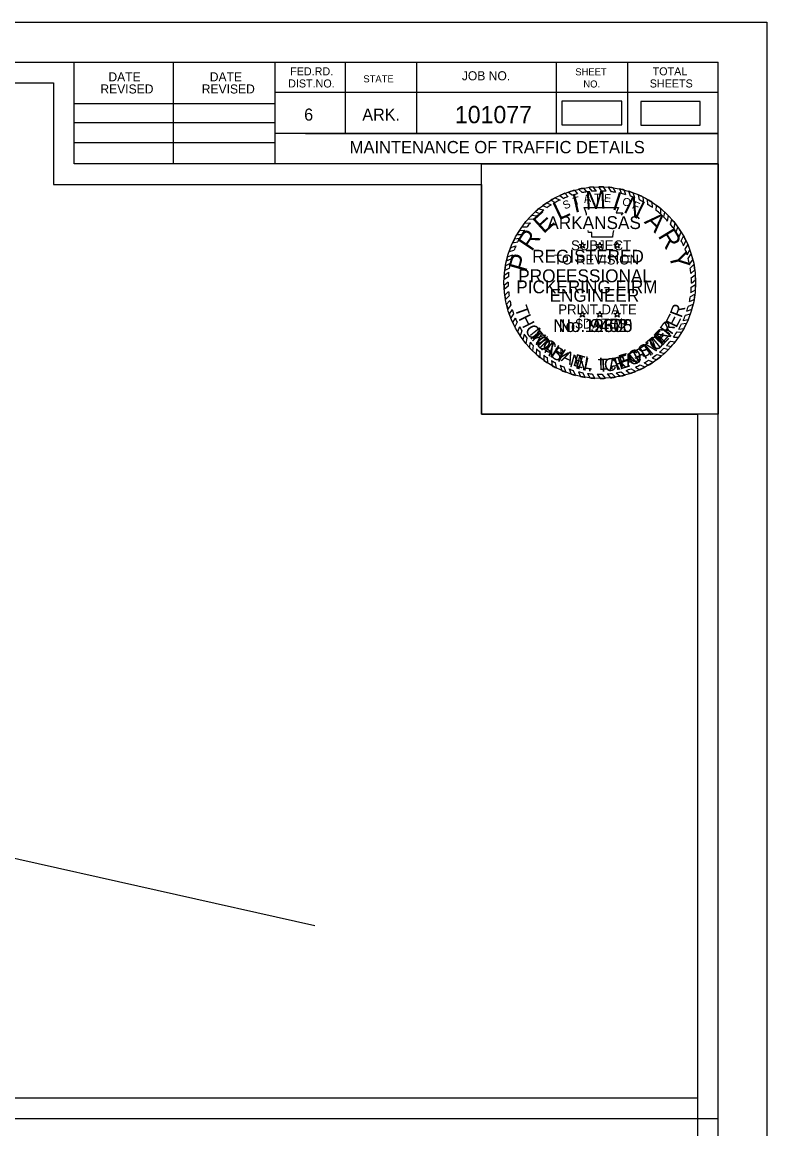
# Model space of a CAD drawing. Extents: x 13528 to 25043, y 7635 to 10612.
# Drawn here: x 21033 to 21396, y 10073 to 10612 of the extents above; entities that cross this region are included whole.
import ezdxf

# ---------------------------------------------------------------- set-up
doc = ezdxf.new("R2010")
doc.units = 0
for name, color, linetype in [('Default', 7, 'Continuous'), ('R_Border Notes', 7, 'Continuous'), ('R_Border Plan-Plan', 7, 'Continuous'), ('R_Draft', 7, 'Continuous'), ('R_Revision Date Text', 7, 'Continuous'), ('STAMP_PE_CRAFTON', 7, 'Continuous'), ('STAMP_PE_FOSTER', 7, 'Continuous'), ('STAMP_PE_SEAL-INFO', 7, 'Continuous'), ('STAMP_PE_TAEGTMEYER', 7, 'Continuous'), ('STAMP_PE_TXT', 7, 'Continuous')]:
    doc.layers.add(name, color=color, linetype=linetype)

msp = doc.modelspace()

# ---------------------------------------------------------------- linework, layer by layer
at = {"layer": 'Default'}
msp.add_line((21022.13, 10206.66), (21175.72, 10172.25), dxfattribs=at)
for points in [[(21295.86, 10561.6), (21325.03, 10561.6), (21325.03, 10573.15), (21295.86, 10573.15)], [(21334.17, 10561.42), (21363.17, 10561.42), (21363.17, 10572.91), (21334.17, 10572.91)]]:
    msp.add_lwpolyline(points, close=True, dxfattribs=at)
at = {"layer": 'R_Border Plan-Plan'}
msp.add_line((19790.89, 10078.42), (21371.79, 10078.42), dxfattribs=at)
at = {"layer": 'R_Draft'}
for p, q in [((19790.89, 10592.07), (21371.79, 10592.07)), ((21058.59, 10542.67), (21058.59, 10592.07)), ((21106.99, 10542.67), (21106.99, 10592.07)), ((21156.29, 10592.07), (21156.29, 10542.67)), ((21190.49, 10592.07), (21190.49, 10557.37)), ((21225.19, 10592.07), (21225.19, 10557.37)), ((21293.09, 10592.07), (21293.09, 10557.37)), ((21327.79, 10592.07), (21327.79, 10557.37)), ((21371.79, 9564.77), (21371.79, 10592.07)), ((21371.79, 10577.37), (21156.29, 10577.37)), ((21371.79, 10577.47), (21371.79, 10577.47)), ((21058.59, 10571.97), (21156.29, 10571.97)), ((21058.59, 10562.67), (21156.29, 10562.67)), ((21058.59, 10552.97), (21156.29, 10552.97)), ((21371.79, 10557.37), (21156.29, 10557.37)), ((21171.09, 10557.37), (21371.79, 10557.37)), ((21371.79, 10542.67), (21058.59, 10542.67))]:
    msp.add_line(p, q, dxfattribs=at)
at = {"layer": 'R_Revision Date Text'}
for points in [[(19728.86, 10611.55), (21395.56, 10611.55), (21395.56, 9544.86), (19728.86, 9544.86)], [(21361.79, 10088.42), (19800.89, 10088.42), (19800.89, 10582.07), (21048.59, 10582.07), (21048.59, 10532.67), (21136.29, 10532.67), (21256.79, 10532.67), (21256.79, 10421.01), (21361.79, 10421.01)], [(19800.89, 10582.07), (21048.59, 10582.07), (21048.59, 10532.67), (21136.29, 10532.67), (21256.79, 10532.67), (21256.79, 10421.01), (21361.79, 10421.01), (21361.79, 9574.77), (19800.89, 9574.77)], [(21256.79, 10542.67), (21371.79, 10542.67), (21371.79, 10421.01), (21256.79, 10421.01)]]:
    msp.add_lwpolyline(points, close=True, dxfattribs=at)
at = {"layer": 'STAMP_PE_SEAL-INFO'}
for p, q in [((21308.98, 10531.19), (21310.38, 10529.28)), ((21312.65, 10529.42), (21311.09, 10531.39)), ((21315.14, 10529.45), (21313.75, 10531.5)), ((21317.43, 10529.34), (21316.14, 10531.46)), ((21319.96, 10529.09), (21318.5, 10531.31)), ((21292.66, 10526.17), (21294.98, 10525.05)), ((21294.81, 10527.23), (21296.76, 10525.86)), ((21297.35, 10528.31), (21298.83, 10526.68)), ((21299.09, 10528.95), (21301, 10527.42)), ((21302.05, 10529.86), (21303.49, 10528.12)), ((21303.99, 10530.35), (21305.77, 10528.63)), ((21306.4, 10530.83), (21307.89, 10528.99)), ((21322.09, 10528.77), (21320.8, 10531.04)), ((21324.9, 10528.17), (21324.03, 10530.47)), ((21326.91, 10527.63), (21326.11, 10529.98)), ((21329.17, 10526.9), (21328.46, 10529.29)), ((21331.26, 10526.1), (21330.54, 10528.58)), ((21333.57, 10525.07), (21333.05, 10527.56)), ((21335.79, 10523.92), (21335.36, 10526.47)), ((21284.5, 10520.73), (21287.14, 10520.23)), ((21286.38, 10522.37), (21288.66, 10521.34)), ((21288.49, 10523.7), (21290.69, 10522.69)), ((21290.42, 10524.92), (21292.58, 10523.81)), ((21306.66, 10521.34), (21323.38, 10521.34)), ((21307.27, 10519.81), (21306.66, 10521.34)), ((21323.38, 10521.34), (21322.26, 10518.88)), ((21337.73, 10522.79), (21337.53, 10525.29)), ((21339.91, 10521.36), (21339.75, 10523.93)), ((21341.71, 10520.02), (21341.88, 10522.46)), ((21343.94, 10518.16), (21344.04, 10520.78)), ((21279.49, 10515.89), (21282.1, 10515.7)), ((21281.1, 10517.61), (21283.82, 10517.41)), ((21282.78, 10519.23), (21285.07, 10518.54)), ((21307.79, 10518.32), (21307.27, 10519.81)), ((21307.82, 10517.75), (21307.79, 10518.32)), ((21322.26, 10518.88), (21325.42, 10518.88)), ((21325.42, 10518.88), (21324.69, 10517.75)), ((21345.5, 10516.7), (21345.85, 10519.19)), ((21347.3, 10514.83), (21347.63, 10517.46)), ((21348.67, 10513.25), (21349.35, 10515.61)), ((21275.2, 10510.27), (21277.78, 10510.44)), ((21276.37, 10511.99), (21278.89, 10511.96)), ((21277.76, 10513.84), (21280.51, 10513.95)), ((21308.78, 10509.2), (21308.65, 10510.29)), ((21320.96, 10510.29), (21320.58, 10508.74)), ((21350.29, 10511.17), (21350.96, 10513.66)), ((21351.39, 10509.59), (21352.28, 10511.91)), ((21352.93, 10507.1), (21353.84, 10509.56)), ((21271.87, 10504.2), (21274.38, 10504.72)), ((21272.81, 10506.15), (21275.3, 10506.47)), ((21273.97, 10508.26), (21276.41, 10508.36)), ((21310.35, 10509.2), (21308.78, 10509.2)), ((21310.35, 10507.05), (21310.35, 10509.2)), ((21320.5, 10507.05), (21310.35, 10507.05)), ((21320.58, 10508.74), (21320.5, 10507.05)), ((21353.93, 10505.27), (21355.06, 10507.49)), ((21355.08, 10502.85), (21356.21, 10505.28)), ((21270.2, 10500.01), (21272.62, 10500.69)), ((21270.95, 10502.04), (21273.47, 10502.77)), ((21355.78, 10501.17), (21357.1, 10503.33)), ((21356.76, 10498.42), (21358.11, 10500.79)), ((21357.3, 10496.6), (21358.76, 10498.86)), ((21270.72, 10494.22), (21268.39, 10492.98)), ((21268.89, 10495.46), (21271.24, 10496.42)), ((21269.42, 10497.49), (21271.8, 10498.34)), ((21357.96, 10493.8), (21359.55, 10496.04)), ((21358.31, 10491.9), (21360.07, 10493.67)), ((21269.99, 10489.75), (21267.81, 10488.35)), ((21270.29, 10491.93), (21268.06, 10490.82)), ((21358.64, 10489.36), (21360.5, 10491.04)), ((21358.8, 10487.27), (21360.75, 10488.73)), ((21269.81, 10487.63), (21267.7, 10486.34)), ((21269.73, 10485.16), (21267.7, 10483.48)), ((21269.76, 10483.13), (21267.8, 10481.5)), ((21358.81, 10482.65), (21360.9, 10484.04)), ((21358.86, 10484.68), (21360.89, 10486.29)), ((21269.93, 10480.65), (21268.07, 10478.87)), ((21270.19, 10478.5), (21268.42, 10476.64)), ((21358.35, 10478.18), (21360.57, 10479.28)), ((21358.61, 10480.12), (21360.78, 10481.4)), ((21270.58, 10476.21), (21268.88, 10474.37)), ((21271.05, 10474.11), (21269.49, 10472.04)), ((21271.67, 10471.88), (21270.19, 10469.79)), ((21356.63, 10470.95), (21359.08, 10471.95)), ((21357.36, 10473.42), (21359.72, 10474.43)), ((21357.9, 10475.68), (21360.18, 10476.66)), ((21272.37, 10469.76), (21270.96, 10467.7)), ((21273.2, 10467.63), (21271.89, 10465.52)), ((21354.88, 10466.48), (21357.32, 10466.96)), ((21355.95, 10469.05), (21358.37, 10469.7)), ((21274.06, 10465.71), (21272.92, 10463.41)), ((21275.23, 10463.42), (21274.28, 10460.97)), ((21276.41, 10461.4), (21275.49, 10459.05)), ((21352.72, 10462.3), (21355.22, 10462.57)), ((21354.08, 10464.8), (21356.52, 10465.14)), ((21277.43, 10459.85), (21276.88, 10457.09)), ((21278.83, 10457.89), (21278.32, 10455.24)), ((21280.35, 10456.01), (21279.92, 10453.41)), ((21348.62, 10456.46), (21350.93, 10456.06)), ((21350.16, 10458.43), (21352.68, 10458.44)), ((21351.86, 10460.9), (21354.24, 10460.87)), ((21281.86, 10454.32), (21281.55, 10451.71)), ((21283.47, 10452.69), (21283.33, 10450.05)), ((21285.2, 10451.13), (21285.18, 10448.48)), ((21343.4, 10451.14), (21345.76, 10450.49)), ((21345.43, 10453), (21347.63, 10452.31)), ((21346.7, 10454.29), (21349.09, 10453.87)), ((21287, 10449.66), (21287.09, 10447.03)), ((21288.69, 10448.41), (21288.87, 10445.82)), ((21290.82, 10447), (21291.13, 10444.44)), ((21292.58, 10445.97), (21293.03, 10443.4)), ((21335.95, 10445.94), (21338.04, 10444.77)), ((21338.02, 10447.16), (21340.27, 10446.18)), ((21339.74, 10448.3), (21341.94, 10447.35)), ((21342.05, 10450.01), (21344.39, 10449.29)), ((21294.98, 10444.72), (21295.76, 10442.11)), ((21296.84, 10443.88), (21297.71, 10441.32)), ((21299.31, 10442.91), (21300.35, 10440.41)), ((21301.35, 10442.24), (21302.49, 10439.79)), ((21303.89, 10441.55), (21304.96, 10439.22)), ((21305.88, 10441.12), (21307.11, 10438.83)), ((21308.38, 10440.71), (21309.58, 10438.51)), ((21310.57, 10440.47), (21311.94, 10438.33)), ((21312.99, 10440.34), (21314.5, 10438.27)), ((21315.29, 10440.33), (21317.01, 10438.35)), ((21317.88, 10440.46), (21319.51, 10438.56)), ((21320.07, 10440.69), (21321.94, 10438.9)), ((21322.3, 10441.04), (21324.24, 10439.35)), ((21324.76, 10441.56), (21326.65, 10439.94)), ((21327.06, 10442.19), (21329.14, 10440.7)), ((21329.52, 10443), (21331.74, 10441.66)), ((21331.62, 10443.82), (21333.73, 10442.52)), ((21333.91, 10444.87), (21336.33, 10443.81))]:
    msp.add_line(p, q, dxfattribs=at)
msp.add_circle((21314.29, 10484.89), 46.61, dxfattribs=at)
for radius, start, end in [(46.61, 93.9381, 96.5517), (46.61, 87.7298, 90.6707), (46.61, 81.9732, 84.8236), (46.61, 117.6544, 120.8099), (46.61, 111.3124, 114.7026), (44.57, 110.3086, 113.1659), (46.61, 105.2339, 109.0352), (44.57, 104.0352, 107.3615), (46.61, 99.7525, 102.7765), (44.57, 98.258, 101.0329), (44.57, 92.1102, 95.0367), (44.57, 85.9628, 88.9097), (44.57, 79.9264, 82.696), (46.61, 75.3125, 77.9426), (44.57, 73.5575, 76.2314), (46.61, 69.6061, 72.3058), (44.57, 67.6248, 70.504), (46.61, 63.1329, 66.2704), (46.61, 129.7326, 132.5376), (46.61, 123.6199, 126.5906), (44.57, 121.9746, 125.11), (44.57, 115.6869, 119.1583), (44.57, 61.1558, 64.3784), (46.61, 56.9003, 60.0942), (44.57, 54.9238, 58.2702), (46.61, 50.3492, 53.7159), (46.61, 135.4021, 138.3031), (44.57, 133.1331, 136.2562), (44.57, 127.5297, 130.9683), (44.57, 48.3016, 52.0395), (44.57, 42.2212, 45.5512), (46.61, 44.3405, 47.3929), (46.61, 38.1247, 41.2316), (46.61, 147.0072, 149.899), (46.61, 141.6056, 144.4486), (44.57, 145.0197, 148.2104), (44.57, 139.301, 142.5873), (44.57, 36.135, 39.5311), (44.57, 29.9032, 33.6645), (46.61, 31.9614, 35.4294), (46.61, 152.864, 155.5189), (44.57, 151.0315, 153.573), (44.57, 23.7732, 27.2211), (46.61, 25.9391, 29.0125), (46.61, 158.4077, 161.0701), (44.57, 156.3402, 159.2319), (44.57, 17.6802, 21.4251), (46.61, 19.9538, 23.3141), (46.61, 13.8421, 17.4447), (46.61, 164.3068, 166.894), (44.57, 167.9048, 170.9039), (44.57, 162.4331, 165.0013), (44.57, 11.5444, 15.2364), (46.61, 7.5852, 10.8621), (46.61, 175.7409, 178.2066), (46.61, 170.0003, 172.6878), (44.57, 173.73, 176.4734), (44.57, 5.7599, 9.0606), (46.61, 1.7215, 4.7268), (46.61, 181.7251, 184.1626), (44.57, 179.6454, 182.2633), (44.57, 353.8632, 357.1274), (44.57, 359.7329, 3.0639), (46.61, 355.7156, 358.9569), (46.61, 187.4204, 190.1927), (44.57, 185.4539, 188.234), (44.57, 348.0778, 351.3435), (46.61, 349.8305, 353.0885), (46.61, 193.0369, 195.9973), (44.57, 191.2274, 193.9858), (44.57, 196.9675, 199.8353), (44.57, 341.777, 345.0925), (46.61, 343.8925, 347.035), (46.61, 198.8967, 201.6281), (44.57, 202.7761, 205.4791), (44.57, 335.6038, 339.1858), (46.61, 337.3837, 340.9933), (46.61, 204.5479, 207.4328), (44.57, 208.7883, 211.7934), (44.57, 329.5549, 333.2076), (46.61, 331.4037, 334.9332), (46.61, 210.8636, 213.6571), (46.61, 216.6115, 219.491), (44.57, 214.1838, 217.2747), (44.57, 220.3909, 223.3056), (44.57, 316.6531, 320.3711), (46.61, 318.2846, 321.8043), (44.57, 323.5851, 327.4407), (46.61, 325.4405, 328.9872), (46.61, 222.48, 225.3801), (44.57, 226.2494, 229.2407), (44.57, 310.7744, 314.3161), (46.61, 312.4518, 315.6633), (46.61, 228.3665, 231.348), (44.57, 232.229, 234.9336), (46.61, 234.295, 236.9452), (44.57, 238.2223, 240.8353), (44.57, 299.0768, 302.1724), (46.61, 300.621, 303.8703), (44.57, 304.823, 308.5143), (46.61, 306.3721, 310.208), (46.61, 240.1977, 242.8613), (44.57, 244.3204, 246.9486), (46.61, 246.576, 249.1558), (44.57, 250.3491, 253.1216), (46.61, 252.5967, 255.3252), (44.57, 256.505, 259.1192), (44.57, 262.3783, 265.2012), (44.57, 268.3215, 271.277), (44.57, 274.6157, 277.4486), (44.57, 280.3459, 283.5814), (46.61, 282.3199, 285.3702), (44.57, 286.6423, 289.9783), (46.61, 288.5709, 291.9733), (44.57, 292.8745, 296.1185), (46.61, 294.6481, 298.2166), (46.61, 258.4433, 261.1398), (46.61, 264.1978, 267.1009), (46.61, 270.2548, 273.3361), (46.61, 276.4239, 279.4357)]:
    msp.add_arc((21314.29, 10484.89), radius, start, end, dxfattribs=at)
at = {"layer": 'STAMP_PE_TXT'}
for p, q in [((21305.43, 10503.46), (21305.8, 10504.63)), ((21305.8, 10504.63), (21306.18, 10503.46)), ((21313.92, 10503.46), (21314.29, 10504.63)), ((21314.29, 10504.63), (21314.67, 10503.46)), ((21322.41, 10503.46), (21322.78, 10504.63)), ((21322.78, 10504.63), (21323.16, 10503.46)), ((21305.19, 10502.74), (21304.2, 10503.46)), ((21304.2, 10503.46), (21305.43, 10503.46)), ((21304.81, 10501.58), (21305.19, 10502.74)), ((21305.8, 10502.3), (21304.81, 10501.58)), ((21306.8, 10501.58), (21305.8, 10502.3)), ((21306.18, 10503.46), (21307.41, 10503.46)), ((21307.41, 10503.46), (21306.42, 10502.74)), ((21306.42, 10502.74), (21306.8, 10501.58)), ((21313.68, 10502.74), (21312.69, 10503.46)), ((21312.69, 10503.46), (21313.92, 10503.46)), ((21313.3, 10501.58), (21313.68, 10502.74)), ((21314.29, 10502.3), (21313.3, 10501.58)), ((21315.29, 10501.58), (21314.29, 10502.3)), ((21314.67, 10503.46), (21315.9, 10503.46)), ((21315.9, 10503.46), (21314.91, 10502.74)), ((21314.91, 10502.74), (21315.29, 10501.58)), ((21322.17, 10502.74), (21321.18, 10503.46)), ((21321.18, 10503.46), (21322.41, 10503.46)), ((21321.79, 10501.58), (21322.17, 10502.74)), ((21322.78, 10502.3), (21321.79, 10501.58)), ((21323.78, 10501.58), (21322.78, 10502.3)), ((21323.16, 10503.46), (21324.39, 10503.46)), ((21324.39, 10503.46), (21323.4, 10502.74)), ((21323.4, 10502.74), (21323.78, 10501.58)), ((21305.19, 10469.21), (21304.2, 10469.93)), ((21304.2, 10469.93), (21305.43, 10469.93)), ((21304.81, 10468.04), (21305.19, 10469.21)), ((21305.8, 10468.76), (21304.81, 10468.04)), ((21305.43, 10469.93), (21305.8, 10471.09)), ((21305.8, 10471.09), (21306.18, 10469.93)), ((21306.8, 10468.04), (21305.8, 10468.76)), ((21306.18, 10469.93), (21307.41, 10469.93)), ((21307.41, 10469.93), (21306.42, 10469.21)), ((21306.42, 10469.21), (21306.8, 10468.04)), ((21313.68, 10469.21), (21312.69, 10469.93)), ((21312.69, 10469.93), (21313.92, 10469.93)), ((21313.3, 10468.04), (21313.68, 10469.21)), ((21314.29, 10468.76), (21313.3, 10468.04)), ((21313.92, 10469.93), (21314.29, 10471.09)), ((21314.29, 10471.09), (21314.67, 10469.93)), ((21315.29, 10468.04), (21314.29, 10468.76)), ((21314.67, 10469.93), (21315.9, 10469.93)), ((21315.9, 10469.93), (21314.91, 10469.21)), ((21314.91, 10469.21), (21315.29, 10468.04)), ((21322.17, 10469.21), (21321.18, 10469.93)), ((21321.18, 10469.93), (21322.41, 10469.93)), ((21321.79, 10468.04), (21322.17, 10469.21)), ((21322.78, 10468.76), (21321.79, 10468.04)), ((21322.41, 10469.93), (21322.78, 10471.09)), ((21322.78, 10471.09), (21323.16, 10469.93)), ((21323.78, 10468.04), (21322.78, 10468.76)), ((21323.16, 10469.93), (21324.39, 10469.93)), ((21324.39, 10469.93), (21323.4, 10469.21)), ((21323.4, 10469.21), (21323.78, 10468.04))]:
    msp.add_line(p, q, dxfattribs=at)

# ---------------------------------------------------------------- texts
at = {"layer": 'R_Border Notes'}
for s, height, p in [('101077', 8.4, (21243.82, 10562.4)), ('MAINTENANCE OF TRAFFIC DETAILS', 6, (21192.64, 10547.77))]:
    msp.add_text(s, height=height, dxfattribs=at).set_placement(p)
at = {"layer": 'R_Draft'}
for s, height, p in [('DATE', 4.396, (21075.28, 10582.75)), ('DATE', 4.396, (21124.58, 10582.75)), ('FED.RD.', 3.91, (21163.69, 10585.67)), ('STATE', 3.42, (21199.29, 10582.27)), ('JOB NO.', 4.396, (21247.19, 10583.27)), ('SHEET', 3.42, (21302.39, 10585.67)), ('TOTAL', 3.91, (21339.99, 10585.67)), ('REVISED', 4.396, (21071.38, 10576.85)), ('REVISED', 4.396, (21120.68, 10576.85)), ('DIST.NO.', 3.91, (21162.69, 10579.77)), ('NO.', 3.42, (21306.29, 10579.77)), ('SHEETS', 3.91, (21338.59, 10579.77)), ('6', 5.86, (21170.49, 10563.67)), ('ARK.', 5.861, (21198.79, 10563.67))]:
    msp.add_text(s, height=height, dxfattribs=at).set_placement(p)
at = {"layer": 'STAMP_PE_CRAFTON'}
msp.add_text('No. 12370', height=6.25, dxfattribs=at).set_placement((21291.6, 10460.87))
for s, rotation, p in [('T', 310.7442, (21279.12, 10459.37)), ('N', 49.2411, (21345.71, 10455)), ('O', 317.6422, (21282.46, 10455.32)), ('N', 324.4537, (21286.69, 10451.39)), ('T', 34.1136, (21337.18, 10448.08)), ('O', 41.8391, (21341.47, 10451.09)), ('Y', 331.1686, (21291.85, 10447.81)), ('A', 20.5125, (21327.7, 10443.66)), ('F', 28.7821, (21332.6, 10445.53)), ('N', 347.4752, (21302.13, 10443.23)), ('C', 6.0117, (21316.65, 10441.59)), ('R', 14.8189, (21322.13, 10442.17)), ('.', 356.8926, (21308.27, 10441.85))]:
    msp.add_text(s, height=6.25, rotation=rotation, dxfattribs=at).set_placement(p)
at = {"layer": 'STAMP_PE_FOSTER'}
msp.add_text('No. 9402', height=6.25, dxfattribs=at).set_placement((21294.22, 10460.87))
for s, rotation, p in [('M', 308.339, (21279.87, 10460)), ('E', 46.9613, (21344.3, 10454.84)), ('R', 54.5031, (21347.92, 10458.94)), ('I', 314.1842, (21283.86, 10455.31)), ('C', 319.8733, (21285.63, 10453.54)), ('T', 39.4194, (21340.01, 10451.09)), ('H', 327.7235, (21290.28, 10449.86)), ('A', 335.7276, (21295.18, 10446.95)), ('F', 15.8691, (21324.47, 10443.66)), ('O', 23.719, (21329.69, 10445.3)), ('S', 31.7234, (21335.25, 10447.95)), ('E', 343.5779, (21300.87, 10444.6)), ('L', 350.8115, (21306.16, 10443.21)), ('L', 1.2666, (21313.86, 10442.43)), ('.', 6.8035, (21319.09, 10442.72))]:
    msp.add_text(s, height=6, rotation=rotation, dxfattribs=at).set_placement(p)
at = {"layer": 'STAMP_PE_SEAL-INFO'}
for s, rotation, p in [('I', 12.5248, (21301.98, 10518.82)), ('M', 3.1074, (21307.47, 10520.36)), ('I', 342.3164, (21319.81, 10520.7)), ('N', 333.9382, (21325.35, 10519.33)), ('L', 25.513, (21294.34, 10515.02)), ('E', 42.3578, (21286.92, 10508.37)), ('A', 315.6579, (21335.52, 10514.2)), ('R', 56.2292, (21281.15, 10499.7)), ('R', 301.3831, (21342.36, 10507.63)), ('P', 73.913, (21278.4, 10489.59)), ('Y', 283.2593, (21347.8, 10498.7))]:
    msp.add_text(s, height=9, rotation=rotation, dxfattribs=at).set_placement(p)
for s, height, p in [('SUBJECT', 4.8, (21300.29, 10500.63)), ('TO REVISION', 4.8, (21291.97, 10493.71)), ('PICKERING FIRM', 6.25, (21273.66, 10479.7)), ('PRINT DATE', 4.8, (21294.08, 10469.46)), ('$DATE$', 4.8, (21302.46, 10462.54))]:
    msp.add_text(s, height=height, dxfattribs=at).set_placement(p)
at = {"layer": 'STAMP_PE_TAEGTMEYER'}
for s, rotation, p in [('T', 289.646, (21272.77, 10472.44)), ('R', 69.57, (21354.02, 10467.46)), ('H', 296.7339, (21274.57, 10467.51)), ('E', 63.0984, (21351.53, 10462.55)), ('O', 303.7708, (21277.53, 10461.97)), ('E', 46.8094, (21344.49, 10453.77)), ('Y', 53.9986, (21348.18, 10457.85)), ('M', 314.2033, (21280.8, 10457.22)), ('A', 321.0594, (21285.61, 10452.4)), ('M', 39.3, (21339.28, 10449.38)), ('S', 327.8239, (21289.74, 10449.18)), ('G', 23.3052, (21329.29, 10444.2)), ('T', 31.466, (21334.79, 10446.66)), ('N', 344.2727, (21299.23, 10444.14)), ('T', 3.0061, (21313.61, 10441.49)), ('A', 8.9826, (21318.85, 10441.77)), ('E', 17.6836, (21324.04, 10442.54)), ('.', 350.6464, (21305.29, 10442.48))]:
    msp.add_text(s, height=6.25, rotation=rotation, dxfattribs=at).set_placement(p)
msp.add_text('No. 19605', height=6.25, dxfattribs=at).set_placement((21291.6, 10460.87))
at = {"layer": 'STAMP_PE_TXT'}
for s, rotation, p in [('T', 16.311, (21301.9, 10522.27)), ('A', 9.0679, (21306.71, 10523.53)), ('T', 1.8248, (21311.65, 10524.18)), ('E', 355.2002, (21316.2, 10524.22)), ('O', 342.2506, (21324.83, 10522.84)), ('S', 23.5541, (21297.29, 10520.4)), ('F', 335.0075, (21329.66, 10521.15))]:
    msp.add_text(s, height=3.91, rotation=rotation, dxfattribs=at).set_placement(p)
for s, p in [('ARKANSAS', (21288.76, 10510.94)), ('REGISTERED', (21281.38, 10494.59)), ('PROFESSIONAL', (21274.64, 10485.08)), ('ENGINEER', (21289.84, 10475.58))]:
    msp.add_text(s, height=6.25, dxfattribs=at).set_placement(p)

doc.saveas('drawing.dxf')
